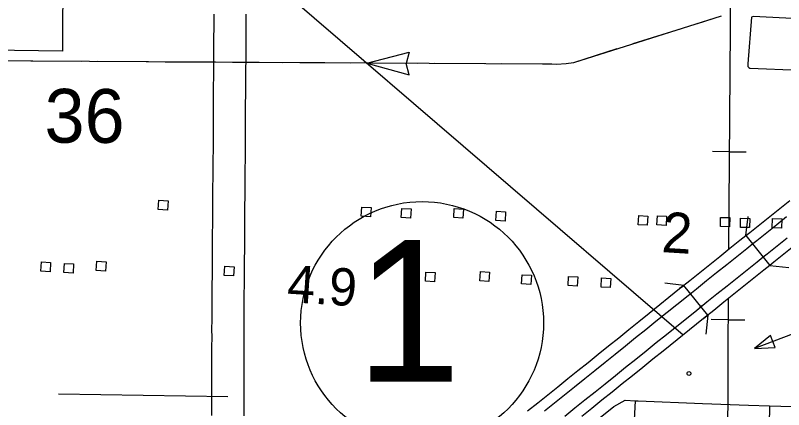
# Model space of a CAD drawing. Extents: x 1366406 to 1373462, y 376856 to 381998.
# Drawn here: x 1369111.5 to 1369209.2, y 379732.3 to 379782.5 of the extents above; entities that cross this region are included whole.
import ezdxf

# ---------------------------------------------------------------- set-up
doc = ezdxf.new("R2010")
doc.units = 0
for name, color, linetype in [('15', 7, 'Continuous'), ('19', 7, 'Continuous'), ('31', 7, 'Continuous'), ('34', 7, 'Continuous'), ('35', 7, 'Continuous'), ('39', 7, 'Continuous'), ('40', 7, 'Continuous'), ('43', 7, 'Continuous'), ('48', 7, 'Continuous'), ('56', 7, 'Continuous'), ('57', 7, 'Continuous'), ('6', 7, 'Continuous'), ('Default', 7, 'Continuous'), ('R_Draft', 7, 'Continuous')]:
    doc.layers.add(name, color=color, linetype=linetype)

msp = doc.modelspace()

# ---------------------------------------------------------------- linework, layer by layer
at = {"layer": '15'}
for points in [[(1369136.757, 379775.721), (1369136.762, 379776.779), (1369136.767, 379777.815), (1369136.773, 379778.834), (1369136.783, 379779.826), (1369136.787, 379780.788), (1369136.786, 379781.731), (1369136.787, 379782.656)], [(1369140.837, 379782.644), (1369140.836, 379781.73), (1369140.837, 379780.781), (1369140.833, 379779.798), (1369140.823, 379778.802), (1369140.817, 379777.793), (1369140.812, 379776.758), (1369140.807, 379775.699)], [(1369136.509, 379731.57), (1369136.509, 379732.654), (1369136.509, 379734.016), (1369136.51, 379734.83), (1369136.51, 379735.921), (1369136.51, 379737.024), (1369136.512, 379738.147), (1369136.523, 379739.268), (1369136.528, 379740.379), (1369136.529, 379741.493), (1369136.528, 379742.613), (1369136.529, 379743.737), (1369136.532, 379744.86), (1369136.539, 379745.983), (1369136.546, 379747.103), (1369136.553, 379748.239), (1369136.584, 379749.333), (1369136.577, 379750.426), (1369136.586, 379751.54), (1369136.595, 379752.638), (1369136.604, 379753.741), (1369136.611, 379754.856), (1369136.616, 379755.843), (1369136.622, 379757.136), (1369136.631, 379758.295), (1369136.643, 379759.459), (1369136.652, 379760.63), (1369136.661, 379761.814), (1369136.671, 379763.011), (1369136.686, 379764.215), (1369136.699, 379765.411), (1369136.709, 379766.888), (1369136.717, 379767.963), (1369136.712, 379768.951), (1369136.71, 379770.123), (1369136.713, 379771.284), (1369136.722, 379772.431), (1369136.736, 379773.552), (1369136.748, 379774.649), (1369136.757, 379775.725)], [(1369140.807, 379775.693), (1369140.798, 379774.611), (1369140.786, 379773.505), (1369140.772, 379772.389), (1369140.763, 379771.263), (1369140.76, 379770.121), (1369140.762, 379768.964), (1369140.767, 379767.958), (1369140.759, 379766.859), (1369140.749, 379765.376), (1369140.736, 379764.168), (1369140.721, 379762.969), (1369140.711, 379761.781), (1369140.702, 379760.598), (1369140.692, 379759.423), (1369140.681, 379758.259), (1369140.672, 379757.11), (1369140.666, 379755.824), (1369140.661, 379754.833), (1369140.653, 379753.711), (1369140.645, 379752.606), (1369140.636, 379751.507), (1369140.627, 379750.423), (1369140.634, 379749.29), (1369140.603, 379748.169), (1369140.596, 379747.078), (1369140.589, 379745.957), (1369140.582, 379744.842), (1369140.579, 379743.73), (1369140.578, 379742.614), (1369140.579, 379741.495), (1369140.578, 379740.368), (1369140.573, 379739.238), (1369140.562, 379738.123), (1369140.56, 379737.021), (1369140.56, 379735.922), (1369140.56, 379734.828), (1369140.559, 379734.015), (1369140.559, 379732.654), (1369140.559, 379731.566)]]:
    msp.add_lwpolyline(points, dxfattribs=at)
at = {"layer": '19'}
for points in [[(1369207.492, 379756.924), (1369208.761, 379757.942), (1369210.03, 379758.958)], [(1369204.447, 379754.492), (1369204.956, 379754.898), (1369206.225, 379755.909), (1369207.492, 379756.924)], [(1369209.622, 379756.868), (1369208.354, 379755.85)], [(1369208.354, 379755.85), (1369207.085, 379754.833), (1369205.814, 379753.821), (1369205.306, 379753.416)], [(1369196.014, 379747.73), (1369196.539, 379748.15), (1369196.014, 379747.73), (1369197.299, 379748.759), (1369198.58, 379749.788), (1369199.857, 379750.816), (1369201.13, 379751.842), (1369202.406, 379752.866), (1369203.683, 379753.883), (1369204.447, 379754.492)], [(1369205.306, 379753.416), (1369204.542, 379752.807), (1369203.266, 379751.791), (1369201.993, 379750.769), (1369200.72, 379749.743), (1369199.443, 379748.715), (1369198.161, 379747.685), (1369196.873, 379746.654), (1369197.285, 379746.982)], [(1369206.621, 379751.771), (1369207.127, 379752.174), (1369208.399, 379753.187), (1369209.672, 379754.207)], [(1369210.532, 379753.131), (1369209.258, 379752.111), (1369207.985, 379751.097), (1369207.48, 379750.695)], [(1369198.833, 379745.525), (1369198.585, 379745.325), (1369198.188, 379745.009), (1369199.479, 379746.042), (1369200.762, 379747.074), (1369202.041, 379748.103), (1369203.313, 379749.128), (1369204.581, 379750.146), (1369205.854, 379751.159), (1369206.621, 379751.771)], [(1369207.48, 379750.695), (1369206.712, 379750.083), (1369205.441, 379749.071), (1369204.176, 379748.055), (1369202.905, 379747.03), (1369201.625, 379746.001), (1369200.341, 379744.968), (1369199.047, 379743.933), (1369199.694, 379744.45)], [(1369176.676, 379732.179), (1369177.955, 379733.205), (1369179.235, 379734.228), (1369180.512, 379735.256), (1369181.79, 379736.284), (1369183.073, 379737.316), (1369184.365, 379738.353), (1369185.661, 379739.395), (1369186.959, 379740.439), (1369188.256, 379741.484), (1369189.549, 379742.53), (1369190.84, 379743.572), (1369192.129, 379744.617), (1369196.014, 379747.73)], [(1369197.079, 379746.818), (1369192.995, 379743.546), (1369191.706, 379742.501), (1369190.415, 379741.459), (1369189.121, 379740.412), (1369187.823, 379739.367), (1369186.524, 379738.322), (1369185.227, 379737.279), (1369183.936, 379736.243), (1369182.653, 379735.211), (1369181.375, 379734.183), (1369180.097, 379733.154), (1369178.816, 379732.13)], [(1369181.415, 379731.512), (1369182.695, 379732.543), (1369183.972, 379733.57), (1369185.255, 379734.601), (1369186.546, 379735.637), (1369187.844, 379736.681), (1369189.144, 379737.727), (1369190.444, 379738.774), (1369191.738, 379739.821), (1369193.03, 379740.863), (1369194.32, 379741.909), (1369198.188, 379745.009)], [(1369199.047, 379743.933), (1369193.896, 379739.793), (1369192.603, 379738.75), (1369191.309, 379737.703), (1369190.008, 379736.654), (1369188.707, 379735.607), (1369187.408, 379734.564), (1369186.117, 379733.527), (1369184.835, 379732.497), (1369183.558, 379731.47)]]:
    msp.add_lwpolyline(points, dxfattribs=at)
at = {"layer": '31'}
for p, q in [((1369190.248, 379731.033), (1369190.397, 379733.458)), ((1369190.397, 379733.458), (1369190.397, 379733.458)), ((1369207.456, 379732.834), (1369207.379, 379730.405))]:
    msp.add_line(p, q, dxfattribs=at)
for points in [[(1369182.542, 379728.708), (1369183.153, 379729.195), (1369186.125, 379731.508), (1369187.645, 379732.719), (1369189.061, 379733.54), (1369190.397, 379733.458)], [(1369190.397, 379733.458), (1369190.738, 379733.437), (1369198.914, 379733.136)], [(1369198.914, 379733.136), (1369204.75, 379732.92), (1369207.456, 379732.834)], [(1369207.456, 379732.834), (1369216.006, 379732.562)]]:
    msp.add_lwpolyline(points, dxfattribs=at)
at = {"layer": '34'}
msp.add_lwpolyline([(1369116.994, 379734.349), (1369138.534, 379734.015)], dxfattribs=at)
at = {"layer": '35'}
msp.add_lwpolyline([(1369217.795, 379781.71), (1369205.362, 379782.36), (1369205.133, 379782.263), (1369204.689, 379776.358), (1369204.668, 379776.025), (1369204.807, 379775.868), (1369204.95, 379775.785), (1369217.579, 379775.287)], dxfattribs=at)
at = {"layer": '39'}
for p, q in [((1369204.447, 379754.492), (1369204.717, 379756.907)), ((1369204.447, 379754.492), (1369207.48, 379750.695)), ((1369207.48, 379750.695), (1369209.895, 379750.425)), ((1369196.539, 379748.15), (1369194.123, 379748.413)), ((1369199.584, 379744.363), (1369196.539, 379748.15)), ((1369199.584, 379744.363), (1369199.322, 379741.947))]:
    msp.add_line(p, q, dxfattribs=at)
at = {"layer": '40'}
for p, q in [((1369202.322, 379765.154), (1369200.183, 379765.169)), ((1369202.322, 379765.154), (1369204.46, 379765.138)), ((1369202.167, 379743.77), (1369200.029, 379743.786)), ((1369202.167, 379743.77), (1369204.306, 379743.755))]:
    msp.add_line(p, q, dxfattribs=at)
for points in [[(1369203.731, 379926.996), (1369203.722, 379914.83), (1369203.646, 379910.711), (1369203.27, 379898.388), (1369203.136, 379878.884), (1369202.778, 379861.356), (1369202.597, 379803.281), (1369202.232, 379752.728)], [(1369202.187, 379746.453), (1369202.141, 379740.092), (1369202.019, 379692.778), (1369201.752, 379646.175), (1369201.658, 379627.263), (1369201.473, 379573.45), (1369201.441, 379561.372), (1369201.238, 379557.987), (1369201.085, 379556.552), (1369200.872, 379555.08), (1369200.455, 379552.926), (1369200.217, 379551.82), (1369199.787, 379550.146), (1369199.44, 379548.992), (1369198.693, 379546.638), (1369197.71, 379544.123), (1369196.563, 379540.969), (1369173.111, 379480.587)]]:
    msp.add_lwpolyline(points, dxfattribs=at)
at = {"layer": '43'}
for p, q in [((1369156.24, 379776.427), (1369161.618, 379777.835)), ((1369161.618, 379777.835), (1369161.227, 379776.407)), ((1369156.24, 379776.427), (1369161.602, 379774.957)), ((1369161.602, 379774.957), (1369161.227, 379776.388))]:
    msp.add_line(p, q, dxfattribs=at)
for points in [[(1369201.292, 379782.409), (1369201.292, 379782.409), (1369182.505, 379776.491), (1369181.567, 379776.349), (1369180.348, 379776.278), (1369178.564, 379776.298), (1369106.473, 379776.714)], [(1369201.292, 379782.409), (1369198.233, 379781.445)], [(1369196.193, 379780.803), (1369190.074, 379778.876)], [(1369188.035, 379778.233), (1369182.505, 379776.491), (1369181.894, 379776.399)], [(1369119.888, 379776.637), (1369113.473, 379776.674)], [(1369128.441, 379776.587), (1369122.026, 379776.624)], [(1369136.995, 379776.538), (1369130.58, 379776.575)], [(1369145.548, 379776.488), (1369139.133, 379776.525)], [(1369150.894, 379776.458), (1369147.686, 379776.476)], [(1369154.101, 379776.439), (1369150.894, 379776.458)], [(1369162.655, 379776.39), (1369156.24, 379776.427)], [(1369171.208, 379776.34), (1369164.793, 379776.377)], [(1369179.762, 379776.285), (1369178.564, 379776.298), (1369173.347, 379776.328)]]:
    msp.add_lwpolyline(points, dxfattribs=at)
at = {"layer": '56'}
for points in [[(1369129.695, 379757.809), (1369129.769, 379758.978), (1369130.941, 379758.904), (1369130.867, 379757.735)], [(1369155.517, 379756.952), (1369155.59, 379758.121), (1369156.762, 379758.048), (1369156.689, 379756.879)], [(1369160.605, 379756.784), (1369160.678, 379757.953), (1369161.85, 379757.879), (1369161.777, 379756.71)], [(1369167.274, 379756.773), (1369167.347, 379757.941), (1369168.519, 379757.868), (1369168.446, 379756.699)], [(1369172.635, 379756.41), (1369172.709, 379757.578), (1369173.881, 379757.505), (1369173.808, 379756.336)], [(1369190.729, 379755.868), (1369190.802, 379757.037), (1369191.975, 379756.963), (1369191.901, 379755.795)], [(1369193.113, 379755.847), (1369193.186, 379757.016), (1369194.358, 379756.942), (1369194.285, 379755.773)], [(1369201.198, 379755.628), (1369201.229, 379756.799), (1369202.403, 379756.768), (1369202.372, 379755.597)], [(1369203.733, 379755.527), (1369203.767, 379756.697), (1369204.941, 379756.663), (1369204.907, 379755.493)], [(1369207.792, 379755.478), (1369207.829, 379756.648), (1369209.002, 379756.612), (1369208.966, 379755.441)], [(1369114.762, 379749.963), (1369114.835, 379751.132), (1369116.008, 379751.058), (1369115.934, 379749.89)], [(1369117.678, 379749.779), (1369117.751, 379750.948), (1369118.923, 379750.874), (1369118.85, 379749.706)], [(1369121.811, 379750.041), (1369121.884, 379751.209), (1369123.056, 379751.136), (1369122.983, 379749.967)], [(1369138.083, 379749.423), (1369138.156, 379750.592), (1369139.328, 379750.518), (1369139.255, 379749.35)], [(1369163.673, 379748.676), (1369163.746, 379749.845), (1369164.918, 379749.771), (1369164.845, 379748.603)], [(1369170.589, 379748.728), (1369170.663, 379749.897), (1369171.835, 379749.824), (1369171.761, 379748.655)], [(1369175.911, 379748.335), (1369175.985, 379749.504), (1369177.157, 379749.431), (1369177.083, 379748.262)], [(1369181.811, 379748.12), (1369181.884, 379749.289), (1369183.056, 379749.215), (1369182.983, 379748.047)], [(1369186.015, 379747.933), (1369186.088, 379749.102), (1369187.26, 379749.028), (1369187.187, 379747.859)]]:
    msp.add_lwpolyline(points, close=True, dxfattribs=at)
at = {"layer": '57'}
msp.add_lwpolyline([(1369217.814, 379744.767), (1369205.536, 379740.127)], dxfattribs=at)
msp.add_lwpolyline([(1369208.147, 379740.23), (1369207.563, 379741.776), (1369205.536, 379740.127)], close=True, dxfattribs=at)
msp.add_circle((1369197.196, 379736.936), 0.243, dxfattribs=at)
at = {"layer": '6'}
for points in [[(1369129.77, 379864), (1369129.862, 379854.494), (1369134.727, 379854.373), (1369134.755, 379852.868), (1369129.061, 379852.949), (1369129.054, 379850.405), (1369117.886, 379850.305), (1369117.785, 379841.849), (1369117.507, 379777.94)], [(1369117.507, 379777.94), (1369096.123, 379778.269), (1369096.005, 379756.945)]]:
    msp.add_lwpolyline(points, dxfattribs=at)
at = {"layer": 'Default'}
msp.add_line((1368826.948, 380059.411), (1369196.471, 379741.863), dxfattribs=at)
at = {"layer": 'R_Draft'}
msp.add_circle((1369163.254, 379743.366), 15.451, dxfattribs=at)

# ---------------------------------------------------------------- texts
at = {"layer": '39'}
msp.add_text('2', height=5.132, rotation=356.41386, dxfattribs=at).set_placement((1369193.637, 379752.395))
at = {"layer": '43'}
msp.add_text('36', height=6.8429, rotation=359.793, dxfattribs=at).set_placement((1369115.222, 379766.317))
at = {"layer": '48'}
msp.add_text('4.9', height=4.752, rotation=356.41386, dxfattribs=at).set_placement((1369145.994, 379746.029))
at = {"layer": 'R_Draft'}
msp.add_text('1', height=18, dxfattribs=at).set_placement((1369154.817, 379735.913))

doc.saveas('drawing.dxf')
